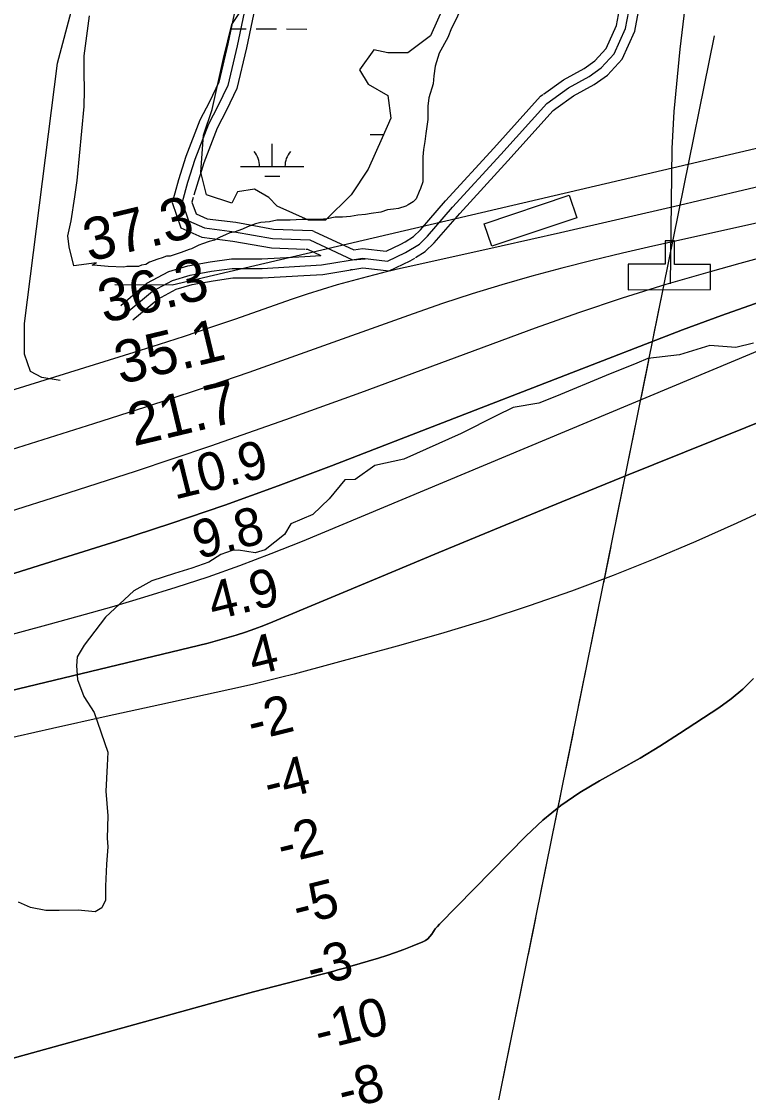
# Model space of a CAD drawing. Extents: x 3245246 to 3283090, y 806824 to 832173.
# Drawn here: x 3260297 to 3261446, y 821555 to 823248 of the extents above; entities that cross this region are included whole.
import ezdxf

# ---------------------------------------------------------------- set-up
doc = ezdxf.new("R2010")
doc.units = 0
for name, color, linetype in [('V-BLDG-OTLN', 7, 'Continuous'), ('V-CHAN-DOCK', 7, 'Continuous'), ('V-RIVR-EDGE', 7, 'Continuous'), ('V-RIVR-FERY', 7, 'Continuous'), ('V-RIVR-RANG', 7, 'Continuous'), ('V-ROAD-CNTR', 7, 'Continuous'), ('V-SITE-VEGE', 7, 'Continuous'), ('V-TOPO-DPTH', 7, 'Continuous'), ('V-TOPO-MAJR', 7, 'Continuous'), ('V-TOPO-MINR', 7, 'Continuous'), ('V-TOPO-SHOR', 7, 'Continuous'), ('V-TOPO-WATR', 7, 'Continuous'), ('V-WETL-SWMP', 7, 'Continuous')]:
    doc.layers.add(name, color=color, linetype=linetype)

msp = doc.modelspace()

# ---------------------------------------------------------------- linework, layer by layer
at = {"layer": 'V-BLDG-OTLN'}
msp.add_lwpolyline([(3261174.3, 822937.4), (3261039.8, 822892.5), (3261027.9, 822928.1), (3261162.4, 822973)], close=True, dxfattribs=at)
at = {"layer": 'V-CHAN-DOCK'}
msp.add_lwpolyline([(3261313.7, 822900.8), (3261313.9, 822864.2), (3261255.3, 822864), (3261255.4, 822823.5), (3261385.5, 822824), (3261385.3, 822863.6), (3261328.8, 822863.4), (3261328.7, 822900.9), (3261313.7, 822900.8)], dxfattribs=at)
at = {"layer": 'V-RIVR-EDGE'}
msp.add_lwpolyline([(3261453.6, 822739.2), (3261425.7, 822732.3), (3261384.4, 822735.5), (3261336.6, 822720.8), (3261286.6, 822714.9), (3261269.2, 822707.5), (3261220.5, 822688.1), (3261142.1, 822655.7), (3261114.3, 822644.4), (3261073.8, 822637.6), (3261046.9, 822624.6), (3260991.6, 822596.5), (3260901.1, 822555.9), (3260855, 822546), (3260824.1, 822523.9), (3260807.5, 822523.5), (3260783.1, 822493.1), (3260757, 822468.4), (3260722.6, 822454.1), (3260712.6, 822437.2), (3260681.6, 822413), (3260666, 822407.8), (3260639.5, 822412.2), (3260629.9, 822411.8), (3260611.6, 822405.3), (3260592.9, 822393.2), (3260565.9, 822383.7), (3260538.5, 822375.5), (3260502.9, 822363.8), (3260474.1, 822347.8), (3260429.7, 822306.2), (3260395.7, 822262), (3260384.8, 822243.7), (3260383.9, 822229.4), (3260385.5, 822208.1), (3260395.5, 822181.1), (3260411.5, 822155.9), (3260433.1, 822093.2), (3260432.2, 822071.9), (3260430.3, 822031.5), (3260433.3, 821992.4), (3260432.3, 821957.2), (3260433.1, 821943.2), (3260430.9, 821916.3), (3260429.5, 821881.1), (3260429.5, 821859.4), (3260423.8, 821847.2), (3260413.3, 821840.7), (3260386.4, 821843.4), (3260356.4, 821842.6), (3260335.1, 821842.6), (3260310.8, 821847.5), (3260292.1, 821855.8)], dxfattribs=at)
at = {"layer": 'V-RIVR-FERY'}
for points in [[(3260522.1, 818934), (3261392, 823224.9)], [(3261296.2, 822752.5), (3261307.8, 822809.6)], [(3261276.4, 822654.6), (3261288, 822711.7)], [(3261256.5, 822556.7), (3261268.1, 822613.8)], [(3261236.7, 822458.7), (3261248.3, 822515.9)], [(3261216.8, 822360.8), (3261228.4, 822418)], [(3261197, 822262.9), (3261208.6, 822320.1)], [(3261177.1, 822165), (3261188.7, 822222.2)], [(3261157.3, 822067.1), (3261168.9, 822124.3)], [(3261137.4, 821969.2), (3261149, 822026.3)], [(3261117.6, 821871.3), (3261129.2, 821928.4)], [(3261097.7, 821773.4), (3261109.3, 821830.5)], [(3261077.9, 821675.5), (3261089.5, 821732.6)], [(3261058, 821577.6), (3261069.6, 821634.7)]]:
    msp.add_lwpolyline(points, dxfattribs=at)
at = {"layer": 'V-ROAD-CNTR'}
for points in [[(3261424.6, 823905.3), (3261404.8, 823779.7), (3261366.3, 823445.6), (3261337.2, 823203.7), (3261327.4, 823105.4), (3261324.3, 823046.9), (3261323.3, 822962.2), (3261321.6, 822833)], [(3260665, 823418.4), (3260638.6, 823287.8), (3260622.9, 823212.4), (3260608.6, 823151.7), (3260593.8, 823120.6), (3260578.8, 823091.5), (3260556.7, 823034.4), (3260544.8, 822997.3), (3260539, 822976.4)], [(3261121.5, 823133), (3261153.4, 823155.4), (3261185.8, 823173.3), (3261202.6, 823185.6), (3261220.7, 823205.1), (3261237, 823241.4), (3261245, 823284.1), (3261258.5, 823301.9), (3261271, 823320.7), (3261307, 823370.6), (3261350.7, 823417.7)], [(3260694.4, 823412.2), (3260668, 823281.8), (3260652.2, 823205.9), (3260637.1, 823141.7), (3260620.7, 823107.3), (3260606.1, 823079.2), (3260585, 823024.4), (3260573.6, 822988.7), (3260569.3, 822973.3)], [(3261141, 823110), (3261169.3, 823130), (3261201.9, 823147.9), (3261222.6, 823163), (3261246.1, 823188.3), (3261265.8, 823232.3), (3261273.2, 823271.6), (3261283, 823284.5), (3261295.7, 823303.7), (3261330.3, 823351.5), (3261372.7, 823397.3)], [(3260653.3, 823284.8), (3260637.5, 823209.1), (3260622.9, 823146.7), (3260607.2, 823113.9), (3260592.5, 823085.3), (3260570.8, 823029.4), (3260559.2, 822993), (3260550.5, 822961.9), (3260560.5, 822932.6), (3260586, 822921.4), (3260633.3, 822915.5), (3260693.6, 822904.7), (3260752.5, 822902.7), (3260819.6, 822871), (3260840, 822872.6)], [(3260463.2, 822787.6), (3260503.6, 822821.6), (3260535.4, 822838.6), (3260563.3, 822846.7), (3260597.1, 822852.9), (3260629.9, 822857.5), (3260677, 822857.4), (3260771, 822862.9), (3260835.8, 822873.7), (3260875.3, 822869.1), (3260903.5, 822882.4), (3260925.5, 822895.9), (3260938.1, 822908.2), (3260978.1, 822954.3), (3261054.1, 823037.6), (3261126.8, 823118.3), (3261161.4, 823142.7), (3261193.8, 823160.6), (3261212.6, 823174.3), (3261233.4, 823196.7), (3261251.4, 823236.8), (3261259.1, 823277.8)], [(3260903.1, 822899.7), (3260916.3, 822907.8), (3260927.2, 822918.5), (3260966.8, 822964.2), (3261043, 823047.7), (3261116.8, 823129.6), (3261120.5, 823132.3)], [(3260919.4, 822874.5), (3260934.8, 822884), (3260949, 822897.9), (3260989.3, 822944.3), (3261065.2, 823027.6), (3261136.8, 823107.1), (3261141, 823110)], [(3260539, 822976.4), (3260534.8, 822961.4), (3260548.4, 822921.5), (3260582, 822906.8), (3260631, 822900.7), (3260692, 822889.8), (3260744.5, 822887.9)], [(3260568.2, 822969.4), (3260566.2, 822962.3), (3260572.6, 822943.7), (3260590, 822936), (3260635.5, 822930.3), (3260695.2, 822919.7), (3260756.1, 822917.5), (3260759, 822916.2)], [(3260759.5, 822915.9), (3260821.8, 822886.6)], [(3260821.8, 822886.6), (3260835.5, 822888.8), (3260872.8, 822884.5), (3260896.4, 822895.6), (3260903.1, 822899.7)], [(3260453.5, 822799.1), (3260495.1, 822834.1), (3260529.8, 822852.6), (3260559.8, 822861.3), (3260594.7, 822867.8), (3260628.8, 822872.5), (3260676.6, 822872.4), (3260744.6, 822876.4)], [(3260744.6, 822876.4), (3260769.8, 822877.9)], [(3260746, 822887.9), (3260748.9, 822887.8), (3260769.8, 822877.9)], [(3260743, 822846.3), (3260772.7, 822848), (3260836.2, 822858.5), (3260877.8, 822853.7), (3260910.7, 822869.2), (3260918.3, 822873.9)], [(3260472.8, 822776.1), (3260512, 822809.1), (3260541.1, 822824.6), (3260566.7, 822832), (3260599.5, 822838.1), (3260630.9, 822842.5), (3260677.4, 822842.4), (3260743, 822846.3)], [(3260816.8, 822855.7), (3260819.5, 822855.9)]]:
    msp.add_lwpolyline(points, dxfattribs=at)
at = {"layer": 'V-SITE-VEGE'}
for points in [[(3260996.1, 823280.3), (3260991.5, 823268.7), (3260983.3, 823250.1), (3260976.3, 823237.3), (3260970.5, 823222.2), (3260956.6, 823197.7), (3260950.7, 823176.8), (3260948.4, 823161.7), (3260947.2, 823148.9), (3260940.3, 823126.8), (3260939.1, 823114), (3260939.1, 823093), (3260935.6, 823070.9), (3260934.4, 823058.1), (3260932.1, 823045.3), (3260930.9, 823033.7)], [(3260930.9, 823033.7), (3260930.9, 822994.1), (3260927.4, 822983.6), (3260925.1, 822979), (3260920.5, 822967.3), (3260915.8, 822962.7), (3260907.7, 822958), (3260904.2, 822955.7), (3260892.5, 822952.2), (3260884.4, 822951.1), (3260875.1, 822949.9), (3260864.6, 822946.4), (3260849.5, 822944.1), (3260840.2, 822942.9), (3260828.5, 822941.8), (3260816.9, 822939.4), (3260804.1, 822938.3), (3260792.5, 822938.3), (3260779.7, 822935.9), (3260768, 822934.8), (3260740.1, 822934.8), (3260721.5, 822933.6), (3260700.5, 822933.6), (3260688.9, 822931.3), (3260674.9, 822930.1), (3260666.8, 822927.8), (3260654, 822923.2), (3260645.8, 822919.7), (3260633, 822915), (3260626, 822913.9), (3260619.1, 822910.4), (3260610.9, 822906.9), (3260601.6, 822902.2), (3260593.5, 822899.9), (3260583, 822896.4), (3260577.2, 822894.1), (3260565.5, 822888.3), (3260562, 822887.1), (3260549.2, 822882.4), (3260541.1, 822880.1), (3260531.8, 822876.6), (3260526, 822876.6), (3260519, 822874.3), (3260512, 822872), (3260499.2, 822867.3), (3260493.4, 822863.8), (3260486.4, 822862.7), (3260481.7, 822860.3), (3260463.1, 822860.3), (3260458.5, 822859.2), (3260434, 822860.4), (3260410.8, 822862.7), (3260408.4, 822862.7), (3260415.4, 822866.2), (3260379.7, 822861.4), (3260372.1, 822891.4), (3260369.8, 822909.2), (3260375.5, 822932.4), (3260381.2, 822970.8), (3260384.6, 822996.2), (3260395.6, 823113.5), (3260396.4, 823139.3), (3260396, 823167.1), (3260396, 823193.3), (3260404.3, 823256.7)]]:
    msp.add_lwpolyline(points, dxfattribs=at)
at = {"layer": 'V-TOPO-DPTH'}
for points in [[(3260276, 822372.8), (3260361.8, 822399.6), (3260447.6, 822426.5), (3260533, 822454.4), (3260618, 822483.3), (3260702.5, 822513.9), (3260786.6, 822545.6), (3261341.5, 822760.6), (3261402.7, 822783.2), (3261464.2, 822804.5)], [(3259963.4, 822114.3), (3260576.7, 822261.7), (3260591.6, 822265.5), (3260606.5, 822269.4), (3260621.3, 822273.6), (3260636.1, 822277.9), (3260650.8, 822282.7), (3260665.3, 822287.7), (3260679.7, 822293.1), (3260694, 822298.9), (3260859.2, 822368.2), (3260956.1, 822408.6), (3261053.2, 822448.8), (3261150.4, 822488.5), (3261247.7, 822527.9), (3261732.3, 822723)], [(3261732.3, 822723), (3261247.7, 822527.9), (3261150.4, 822488.5), (3261053.2, 822448.8), (3260956.1, 822408.6), (3260859.2, 822368.2), (3260694, 822298.9), (3260679.7, 822293.1), (3260665.3, 822287.7), (3260650.8, 822282.7), (3260636.1, 822277.9), (3260621.3, 822273.6), (3260606.5, 822269.4), (3260591.6, 822265.5), (3260576.7, 822261.7), (3259963.4, 822114.3)], [(3260102.6, 821559.3), (3260593.7, 821695.3), (3260628.4, 821704.8), (3260663.2, 821714.2), (3260698.1, 821723.4), (3260733, 821732.5), (3260790.1, 821747.2), (3260796.4, 821748.9), (3260802.8, 821750.6), (3260809.1, 821752.4), (3260815.4, 821754.2), (3260860.8, 821767.7), (3260874.3, 821771.9), (3260887.7, 821776.4), (3260900.9, 821781.2), (3260914, 821786.3), (3260930.9, 821793.1), (3260935.2, 821795.4), (3260939.1, 821798.1), (3260942.3, 821801.6), (3260945.2, 821805.6), (3260947.8, 821809.9), (3260950.7, 821814), (3260953.9, 821817.8), (3260957.2, 821821.5), (3261094.1, 821960.9), (3261120.8, 821985.7), (3261148.9, 822008.7), (3261178.9, 822029.1), (3261210.3, 822047.7), (3261242.4, 822065.4), (3261274.2, 822083.6), (3261305.5, 822102.7), (3261336.4, 822122.4), (3261398.7, 822163.2), (3261418.2, 822177.4), (3261436.6, 822192.6), (3261453.5, 822209.6)], [(3261453.5, 822209.6), (3261436.6, 822192.6), (3261418.2, 822177.4), (3261398.7, 822163.2), (3261336.4, 822122.4), (3261305.5, 822102.7), (3261274.2, 822083.6), (3261242.4, 822065.4), (3261210.3, 822047.7), (3261178.9, 822029.1), (3261148.9, 822008.7), (3261120.8, 821985.7), (3261094.1, 821960.9), (3260957.2, 821821.5), (3260953.9, 821817.8), (3260950.7, 821814), (3260947.8, 821809.9), (3260945.2, 821805.6), (3260942.3, 821801.6), (3260939.1, 821798.1), (3260935.2, 821795.4), (3260930.9, 821793.1), (3260914, 821786.3), (3260900.9, 821781.2), (3260887.7, 821776.4), (3260874.3, 821771.9), (3260860.8, 821767.7), (3260815.4, 821754.2), (3260809.1, 821752.4), (3260802.8, 821750.6), (3260796.4, 821748.9), (3260790.1, 821747.2), (3260733, 821732.5), (3260698.1, 821723.4), (3260663.2, 821714.2), (3260628.4, 821704.8), (3260593.7, 821695.3), (3260102.6, 821559.3)]]:
    msp.add_lwpolyline(points, dxfattribs=at)
at = {"layer": 'V-TOPO-MAJR'}
msp.add_lwpolyline([(3261642.1, 823029.3), (3261429.5, 822978.9), (3261335.9, 822956.9), (3261242.2, 822935.2), (3261148.5, 822913.9), (3261054.6, 822892.8), (3260915.2, 822861.8), (3260891.1, 822856.3), (3260867, 822850.5), (3260843.1, 822844.4), (3260819.2, 822838), (3260795.4, 822831.3), (3260771.7, 822824.2), (3260748.2, 822816.6), (3260724.7, 822808.7), (3260633.4, 822776.9), (3260593.8, 822763.4), (3260554.1, 822750.1), (3260514.2, 822737.2), (3260474.3, 822724.6), (3259846.9, 822529.5)], dxfattribs=at)
at = {"layer": 'V-TOPO-MINR'}
for points in [[(3261678.1, 823219.3), (3261680.3, 823200.8), (3261692.4, 823101.5), (3260534.7, 822830.8), (3260444.2, 822831.3)], [(3261688.5, 822979.8), (3261294.3, 822892.6), (3261246.3, 822881.6), (3261198.5, 822870.1), (3261150.8, 822857.9), (3261103.2, 822845.2), (3261055.9, 822831.6), (3261008.8, 822817.3), (3260962, 822801.9), (3260915.5, 822785.8), (3260737.1, 822721.7), (3260655.9, 822693), (3260574.4, 822665.1), (3260492.7, 822638.1), (3260410.7, 822611.7), (3260059.6, 822501.3)], [(3261478.5, 822878), (3261432, 822865.4), (3261384.9, 822852.2), (3261315.2, 822831.9), (3261245.9, 822810.4), (3261177.1, 822787.2), (3261108.7, 822762.9), (3260832.3, 822660.7), (3260714.2, 822618), (3260595.6, 822576.4), (3260476.5, 822536.6), (3260357, 822497.9), (3260277.1, 822472.6)], [(3261464.2, 822804.5), (3261402.7, 822783.2), (3261341.5, 822760.6), (3260786.6, 822545.6), (3260702.5, 822513.9), (3260618, 822483.3), (3260533, 822454.4), (3260447.6, 822426.5), (3260361.8, 822399.6), (3260276, 822372.8)], [(3261611, 822789.9), (3260740.1, 822426), (3260690.8, 822406.2), (3260641.1, 822387.3), (3260591, 822369.8), (3260540.5, 822353.2), (3260489.7, 822337.6), (3260438.8, 822322.4), (3260387.7, 822307.8), (3260336.5, 822293.6), (3259986.7, 822198.7)], [(3261751.8, 822605), (3261427, 822454.9), (3261362.5, 822426), (3261297.5, 822398.3), (3261231.9, 822372.3), (3261165.8, 822347.3), (3261099, 822324.1), (3261031.9, 822302), (3260964.3, 822281.5), (3260896.3, 822262.2), (3260727.4, 822216.5), (3260706.3, 822211), (3260685.2, 822205.7), (3260664, 822200.7), (3260642.8, 822195.8), (3260515.6, 822168.1), (3260430.8, 822149.4), (3260346, 822130.6), (3260261.3, 822111.6)], [(3261453.5, 822209.6), (3261436.6, 822192.6), (3261418.2, 822177.4), (3261398.7, 822163.2), (3261336.4, 822122.4), (3261305.5, 822102.7), (3261274.2, 822083.6), (3261242.4, 822065.4), (3261210.3, 822047.7), (3261178.9, 822029.1), (3261148.9, 822008.7), (3261120.8, 821985.7), (3261094.1, 821960.9), (3260957.2, 821821.5), (3260953.9, 821817.8), (3260950.7, 821814), (3260947.8, 821809.9), (3260945.2, 821805.6), (3260942.3, 821801.6), (3260939.1, 821798.1), (3260935.2, 821795.4), (3260930.9, 821793.1), (3260914, 821786.3), (3260900.9, 821781.2), (3260887.7, 821776.4), (3260874.3, 821771.9), (3260860.8, 821767.7), (3260815.4, 821754.2), (3260809.1, 821752.4), (3260802.8, 821750.6), (3260796.4, 821748.9), (3260790.1, 821747.2), (3260733, 821732.5), (3260698.1, 821723.4), (3260663.2, 821714.2), (3260628.4, 821704.8), (3260593.7, 821695.3), (3260102.6, 821559.3)]]:
    msp.add_lwpolyline(points, dxfattribs=at)
at = {"layer": 'V-TOPO-SHOR'}
msp.add_lwpolyline([(3260357.8, 822680.4), (3260329.1, 822685.3), (3260310.8, 822694.4), (3260301.7, 822721.8), (3260301.7, 822770.6), (3260353.5, 823181.8), (3260399.1, 823352.4)], dxfattribs=at)
at = {"layer": 'V-TOPO-WATR'}
msp.add_lwpolyline([(3261732.3, 822723), (3261247.7, 822527.9), (3261150.4, 822488.5), (3261053.2, 822448.8), (3260956.1, 822408.6), (3260859.2, 822368.2), (3260694, 822298.9), (3260679.7, 822293.1), (3260665.3, 822287.7), (3260650.8, 822282.7), (3260636.1, 822277.9), (3260621.3, 822273.6), (3260606.5, 822269.4), (3260591.6, 822265.5), (3260576.7, 822261.7), (3259963.4, 822114.3)], dxfattribs=at)
at = {"layer": 'V-WETL-SWMP'}
for p, q in [((3260627.5, 823235.8), (3260651.8, 823235.8)), ((3260667.8, 823235.8), (3260699.8, 823235.8)), ((3260715.8, 823235.8), (3260747.8, 823235.7)), ((3260847.7, 823069.2), (3260869.2, 823069.2)), ((3260693.1, 823018.5), (3260693.1, 823054.5)), ((3260643.1, 823018.5), (3260743.1, 823018.5)), ((3260681.1, 823003.1), (3260705.1, 823003.1))]:
    msp.add_line(p, q, dxfattribs=at)
msp.add_lwpolyline([(3260965.3, 823274.4), (3260942.9, 823225), (3260907.1, 823198.1), (3260875.7, 823198.1), (3260853.3, 823202.6), (3260830.9, 823171.2), (3260844.4, 823148.8), (3260875.7, 823130.9), (3260880.2, 823095), (3260866.8, 823063.6), (3260844.4, 823014.3), (3260817.5, 822973.9), (3260777.2, 822933.6), (3260750.3, 822933.6), (3260701, 822956), (3260687.6, 822969.5), (3260665.1, 822982.9), (3260638.3, 822978.4), (3260629.3, 822960.5), (3260589, 822973.9), (3260580, 823009.8), (3260584.5, 823068.1), (3260597.9, 823108.5), (3260615.9, 823189.2), (3260629.3, 823243), (3260656.2, 823283.3)], dxfattribs=at)
for centre, start, end in [((3260899.4, 823189.7), 40.2804, 40.7468), ((3260637.8, 823019), 359.2032, 40.7468), ((3260748.3, 823019), 139.2032, 180.7468)]:
    msp.add_arc(centre, 35.2, start, end, dxfattribs=at)

# ---------------------------------------------------------------- texts
at = {"layer": 'V-RIVR-RANG'}
for s, height, rotation, p in [('37.3', 67, 13.4883, (3260403.5, 822867.8)), ('36.3', 67, 13.4883, (3260427.1, 822770.6)), ('35.1', 67, 13.4883, (3260453, 822674)), ('21.7', 67, 13.4883, (3260474.2, 822576.2)), ('10.9', 60, 13.9381, (3260538.8, 822491.9)), ('9.8', 60, 13.9381, (3260575.9, 822398)), ('4.9', 60, 13.9381, (3260600.1, 822301)), ('4', 60, 13.9381, (3260663.6, 822213.7)), ('-2', 60, 13.9381, (3260661.7, 822110.2)), ('-4', 60, 13.9381, (3260687.8, 822013.7)), ('-2', 60, 13.9381, (3260708.8, 821915.9)), ('-5', 60, 13.9381, (3260733.3, 821818.9)), ('-3', 60, 13.9381, (3260755.5, 821721.4)), ('-10', 60, 13.9381, (3260767.8, 821621.4)), ('-8', 60, 13.9381, (3260804.9, 821527.6))]:
    msp.add_text(s, height=height, rotation=rotation, dxfattribs=at).set_placement(p)

doc.saveas('drawing.dxf')
